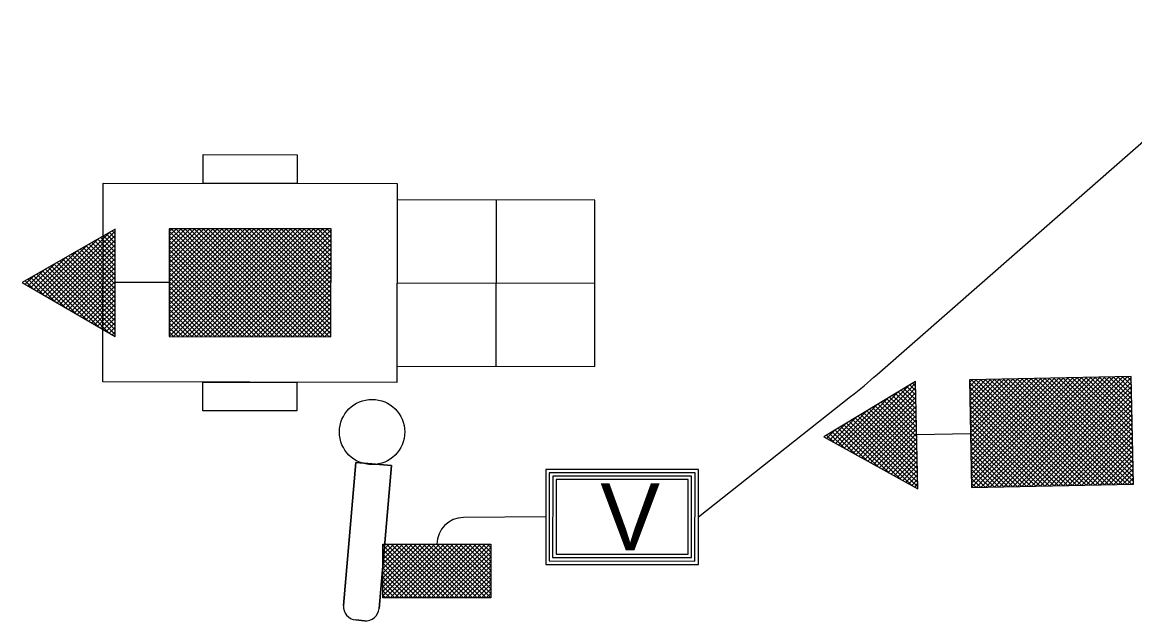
# Model space of a CAD drawing. Extents: x 584850 to 602551, y 145475 to 158627.
# Drawn here: x 585770 to 585852.5, y 152623.4 to 152667.8 of the extents above; entities that cross this region are included whole.
import ezdxf

# ---------------------------------------------------------------- set-up
doc = ezdxf.new("R2010")
doc.units = 0
doc.layers.add('Default', color=7, linetype='Continuous')

msp = doc.modelspace()

# ---------------------------------------------------------------- linework, layer by layer
at = {"layer": 'Default'}
for p, q in [((585833.355, 152641.699), (585863.133, 152667.828)), ((585805.092, 152654.647), (585805.071, 152642.296)), ((585771.677, 152647.517), (585776.391, 152652.214)), ((585771.892, 152647.392), (585776.857, 152652.341)), ((585772.107, 152647.267), (585776.857, 152652.001)), ((585776.855, 152650.773), (585775.773, 152651.858)), ((585776.855, 152651.113), (585775.988, 152651.983)), ((585776.856, 152651.452), (585776.203, 152652.106)), ((585776.856, 152651.792), (585776.419, 152652.23)), ((585776.857, 152652.131), (585776.634, 152652.354)), ((585776.857, 152652.47), (585776.849, 152652.478)), ((585780.843, 152644.513), (585788.857, 152652.499)), ((585780.844, 152645.192), (585788.178, 152652.501)), ((585780.844, 152644.853), (585788.518, 152652.5)), ((585780.845, 152645.531), (585787.839, 152652.501)), ((585780.846, 152646.21), (585787.16, 152652.502)), ((585780.846, 152645.871), (585787.5, 152652.502)), ((585780.847, 152646.889), (585786.481, 152652.504)), ((585780.847, 152646.55), (585786.821, 152652.503)), ((585780.848, 152647.229), (585786.142, 152652.504)), ((585780.849, 152647.907), (585785.463, 152652.505)), ((585780.849, 152647.568), (585785.803, 152652.505)), ((585780.85, 152648.247), (585785.124, 152652.506)), ((585780.85, 152648.586), (585784.784, 152652.506)), ((585780.851, 152649.265), (585784.105, 152652.508)), ((585780.851, 152648.926), (585784.445, 152652.507)), ((585780.852, 152649.604), (585783.766, 152652.508)), ((585780.853, 152649.944), (585783.427, 152652.509)), ((585780.853, 152650.283), (585783.087, 152652.509)), ((585780.854, 152650.962), (585782.408, 152652.511)), ((585780.854, 152650.623), (585782.748, 152652.51)), ((585780.855, 152651.301), (585782.069, 152652.511)), ((585780.856, 152651.641), (585781.73, 152652.512)), ((585780.856, 152651.98), (585781.39, 152652.512)), ((585788.31, 152644.5), (585780.856, 152651.98)), ((585780.857, 152652.32), (585781.051, 152652.513)), ((585788.65, 152644.5), (585780.857, 152652.32)), ((585788.989, 152644.499), (585781.003, 152652.513)), ((585781.183, 152644.513), (585789.197, 152652.499)), ((585789.329, 152644.499), (585781.343, 152652.512)), ((585781.522, 152644.512), (585789.536, 152652.498)), ((585789.668, 152644.498), (585781.682, 152652.512)), ((585781.861, 152644.511), (585789.875, 152652.498)), ((585790.007, 152644.497), (585782.021, 152652.511)), ((585782.201, 152644.511), (585790.215, 152652.497)), ((585790.347, 152644.497), (585782.361, 152652.511)), ((585782.54, 152644.51), (585790.554, 152652.497)), ((585790.686, 152644.496), (585782.7, 152652.51)), ((585782.88, 152644.51), (585790.894, 152652.496)), ((585791.026, 152644.496), (585783.04, 152652.509)), ((585783.219, 152644.509), (585791.233, 152652.495)), ((585791.365, 152644.495), (585783.379, 152652.509)), ((585783.559, 152644.509), (585791.573, 152652.495)), ((585791.704, 152644.495), (585783.718, 152652.508)), ((585783.898, 152644.508), (585791.912, 152652.494)), ((585792.044, 152644.494), (585784.058, 152652.508)), ((585784.237, 152644.507), (585792.251, 152652.494)), ((585792.383, 152644.493), (585784.397, 152652.507)), ((585784.577, 152644.507), (585792.591, 152652.493)), ((585792.723, 152644.493), (585784.737, 152652.507)), ((585784.916, 152644.506), (585792.857, 152652.42)), ((585792.844, 152644.711), (585785.076, 152652.506)), ((585785.256, 152644.506), (585792.857, 152652.081)), ((585792.845, 152645.05), (585785.415, 152652.505)), ((585792.845, 152645.39), (585785.755, 152652.505)), ((585792.846, 152645.729), (585786.094, 152652.504)), ((585792.847, 152646.069), (585786.434, 152652.504)), ((585792.847, 152646.408), (585786.773, 152652.503)), ((585792.848, 152646.748), (585787.113, 152652.502)), ((585792.848, 152647.087), (585787.452, 152652.502)), ((585792.849, 152647.426), (585787.791, 152652.501)), ((585792.849, 152647.766), (585788.131, 152652.501)), ((585792.85, 152648.105), (585788.47, 152652.5)), ((585792.851, 152648.445), (585788.81, 152652.5)), ((585792.851, 152648.784), (585789.149, 152652.499)), ((585792.852, 152649.123), (585789.488, 152652.498)), ((585792.852, 152649.463), (585789.828, 152652.498)), ((585792.853, 152649.802), (585790.167, 152652.497)), ((585792.853, 152650.142), (585790.507, 152652.497)), ((585792.854, 152650.481), (585790.846, 152652.496)), ((585792.855, 152650.82), (585791.185, 152652.495)), ((585792.855, 152651.16), (585791.525, 152652.495)), ((585792.856, 152651.499), (585791.864, 152652.494)), ((585792.856, 152651.839), (585792.204, 152652.494)), ((585792.857, 152652.178), (585792.543, 152652.493)), ((585771.247, 152647.766), (585774.782, 152651.289)), ((585771.462, 152647.641), (585775.586, 152651.751)), ((585772.322, 152647.143), (585776.856, 152651.662)), ((585772.537, 152647.018), (585776.855, 152651.322)), ((585776.851, 152648.737), (585774.481, 152651.115)), ((585776.852, 152649.076), (585774.696, 152651.239)), ((585776.852, 152649.416), (585774.911, 152651.363)), ((585776.853, 152649.755), (585775.127, 152651.487)), ((585776.853, 152650.095), (585775.342, 152651.611)), ((585776.854, 152650.434), (585775.557, 152651.735)), ((585787.631, 152644.502), (585780.855, 152651.301)), ((585787.971, 152644.501), (585780.856, 152651.641)), ((585785.595, 152644.505), (585792.856, 152651.741)), ((585785.934, 152644.504), (585792.856, 152651.402)), ((585786.274, 152644.504), (585792.855, 152651.063)), ((585770.817, 152648.015), (585773.174, 152650.364)), ((585771.032, 152647.891), (585773.978, 152650.826)), ((585772.751, 152646.894), (585776.855, 152650.983)), ((585772.967, 152646.769), (585776.854, 152650.643)), ((585776.847, 152646.361), (585772.973, 152650.248)), ((585773.181, 152646.644), (585776.854, 152650.304)), ((585776.848, 152646.7), (585773.188, 152650.372)), ((585776.848, 152647.04), (585773.404, 152650.496)), ((585776.849, 152647.379), (585773.619, 152650.62)), ((585776.849, 152647.719), (585773.834, 152650.744)), ((585776.85, 152648.058), (585774.05, 152650.867)), ((585776.85, 152648.397), (585774.265, 152650.991)), ((585786.613, 152644.503), (585780.853, 152650.283)), ((585787.292, 152644.502), (585780.854, 152650.962)), ((585786.953, 152644.503), (585780.854, 152650.623)), ((585786.613, 152644.503), (585792.854, 152650.723)), ((585786.953, 152644.503), (585792.854, 152650.384)), ((585770.388, 152648.265), (585771.566, 152649.439)), ((585770.603, 152648.14), (585772.37, 152649.901)), ((585775.578, 152645.254), (585771.465, 152649.381)), ((585776.381, 152644.788), (585771.681, 152649.505)), ((585776.844, 152644.664), (585771.896, 152649.629)), ((585776.845, 152645.003), (585772.111, 152649.753)), ((585776.845, 152645.343), (585772.327, 152649.876)), ((585776.846, 152645.682), (585772.542, 152650)), ((585776.846, 152646.022), (585772.757, 152650.124)), ((585773.396, 152646.519), (585776.853, 152649.965)), ((585773.611, 152646.395), (585776.853, 152649.625)), ((585785.934, 152644.504), (585780.852, 152649.604)), ((585786.274, 152644.504), (585780.853, 152649.944)), ((585787.292, 152644.502), (585792.853, 152650.044)), ((585787.631, 152644.502), (585792.853, 152649.705)), ((585787.971, 152644.501), (585792.852, 152649.366)), ((585770.172, 152648.389), (585770.762, 152648.976)), ((585770.76, 152648.048), (585770.173, 152648.637)), ((585771.564, 152647.583), (585770.389, 152648.762)), ((585772.366, 152647.117), (585770.604, 152648.885)), ((585773.169, 152646.651), (585770.819, 152649.009)), ((585773.972, 152646.185), (585771.035, 152649.133)), ((585774.775, 152645.72), (585771.25, 152649.257)), ((585773.826, 152646.27), (585776.852, 152649.286)), ((585774.041, 152646.145), (585776.851, 152648.946)), ((585774.256, 152646.021), (585776.851, 152648.607)), ((585784.916, 152644.506), (585780.85, 152648.586)), ((585785.595, 152644.505), (585780.851, 152649.265)), ((585785.256, 152644.506), (585780.851, 152648.926)), ((585788.31, 152644.5), (585792.852, 152649.026)), ((585788.65, 152644.5), (585792.851, 152648.687)), ((585769.958, 152648.514), (585769.958, 152648.514)), ((585774.471, 152645.896), (585776.85, 152648.268)), ((585774.686, 152645.772), (585776.85, 152647.928)), ((585780.85, 152648.513), (585776.851, 152648.52)), ((585784.237, 152644.507), (585780.849, 152647.907)), ((585784.577, 152644.507), (585780.85, 152648.247)), ((585788.989, 152644.499), (585792.85, 152648.347)), ((585789.329, 152644.499), (585792.85, 152648.008)), ((585812.418, 152648.459), (585797.744, 152648.484)), ((585774.901, 152645.647), (585776.849, 152647.589)), ((585775.116, 152645.523), (585776.849, 152647.249)), ((585775.331, 152645.398), (585776.848, 152646.91)), ((585783.219, 152644.509), (585780.847, 152646.889)), ((585783.559, 152644.509), (585780.848, 152647.229)), ((585783.898, 152644.508), (585780.849, 152647.568)), ((585789.668, 152644.498), (585792.849, 152647.669)), ((585790.007, 152644.497), (585792.849, 152647.329)), ((585790.347, 152644.497), (585792.848, 152646.99)), ((585775.546, 152645.273), (585776.847, 152646.571)), ((585775.76, 152645.148), (585776.847, 152646.231)), ((585782.54, 152644.51), (585780.846, 152646.21)), ((585782.88, 152644.51), (585780.847, 152646.55)), ((585790.686, 152644.496), (585792.848, 152646.65)), ((585791.026, 152644.496), (585792.847, 152646.311)), ((585775.975, 152645.024), (585776.846, 152645.892)), ((585776.19, 152644.899), (585776.846, 152645.552)), ((585781.861, 152644.511), (585780.845, 152645.531)), ((585782.201, 152644.511), (585780.846, 152645.871)), ((585791.365, 152644.495), (585792.846, 152645.972)), ((585791.704, 152644.495), (585792.846, 152645.632)), ((585792.044, 152644.494), (585792.845, 152645.293)), ((585776.405, 152644.774), (585776.845, 152645.213)), ((585776.62, 152644.65), (585776.844, 152644.874)), ((585776.835, 152644.525), (585776.844, 152644.534)), ((585781.522, 152644.512), (585780.844, 152645.192)), ((585781.183, 152644.513), (585780.844, 152644.853)), ((585792.383, 152644.493), (585792.845, 152644.953)), ((585792.723, 152644.493), (585792.844, 152644.614)), ((585836.198, 152641.173), (585836.19, 152641.181)), ((585840.2, 152641.111), (585840.389, 152641.308)), ((585848.164, 152633.465), (585840.2, 152641.111)), ((585840.207, 152640.771), (585840.729, 152641.315)), ((585840.214, 152640.432), (585841.068, 152641.322)), ((585840.221, 152640.093), (585841.408, 152641.329)), ((585840.228, 152639.754), (585841.747, 152641.336)), ((585840.235, 152639.414), (585842.086, 152641.343)), ((585840.241, 152639.075), (585842.426, 152641.35)), ((585840.248, 152638.735), (585842.765, 152641.357)), ((585840.255, 152638.396), (585843.104, 152641.364)), ((585840.262, 152638.057), (585843.443, 152641.371)), ((585840.269, 152637.718), (585843.783, 152641.377)), ((585840.276, 152637.378), (585844.122, 152641.384)), ((585840.283, 152637.039), (585844.462, 152641.391)), ((585840.29, 152636.699), (585844.801, 152641.398)), ((585840.297, 152636.36), (585845.14, 152641.405)), ((585840.304, 152636.021), (585845.479, 152641.412)), ((585840.311, 152635.682), (585845.819, 152641.419)), ((585840.318, 152635.342), (585846.158, 152641.426)), ((585840.324, 152635.003), (585846.498, 152641.433)), ((585840.331, 152634.663), (585846.837, 152641.44)), ((585840.338, 152634.324), (585847.177, 152641.447)), ((585848.503, 152633.472), (585840.342, 152641.307)), ((585840.345, 152633.985), (585847.515, 152641.454)), ((585840.352, 152633.645), (585847.855, 152641.46)), ((585840.359, 152633.306), (585848.194, 152641.467)), ((585848.843, 152633.479), (585840.681, 152641.314)), ((585840.698, 152633.313), (585848.534, 152641.474)), ((585849.182, 152633.486), (585841.02, 152641.321)), ((585841.038, 152633.32), (585848.873, 152641.481)), ((585849.521, 152633.493), (585841.36, 152641.328)), ((585841.377, 152633.327), (585849.212, 152641.488)), ((585849.861, 152633.5), (585841.699, 152641.335)), ((585841.716, 152633.334), (585849.552, 152641.495)), ((585850.2, 152633.507), (585842.039, 152641.342)), ((585842.056, 152633.341), (585849.891, 152641.502)), ((585850.539, 152633.514), (585842.378, 152641.349)), ((585842.395, 152633.348), (585850.23, 152641.509)), ((585850.878, 152633.52), (585842.717, 152641.356)), ((585842.735, 152633.354), (585850.57, 152641.516)), ((585851.218, 152633.527), (585843.056, 152641.363)), ((585843.074, 152633.361), (585850.909, 152641.523)), ((585851.557, 152633.534), (585843.396, 152641.37)), ((585843.413, 152633.368), (585851.248, 152641.53)), ((585851.897, 152633.541), (585843.735, 152641.376)), ((585843.752, 152633.375), (585851.588, 152641.537)), ((585852.236, 152633.548), (585844.075, 152641.383)), ((585844.092, 152633.382), (585851.927, 152641.543)), ((585852.353, 152633.769), (585844.414, 152641.39)), ((585844.431, 152633.389), (585852.195, 152641.476)), ((585852.346, 152634.108), (585844.753, 152641.397)), ((585844.771, 152633.396), (585852.202, 152641.137)), ((585852.339, 152634.447), (585845.092, 152641.404)), ((585852.332, 152634.787), (585845.432, 152641.411)), ((585852.325, 152635.126), (585845.771, 152641.418)), ((585852.318, 152635.466), (585846.111, 152641.425)), ((585852.311, 152635.805), (585846.45, 152641.432)), ((585852.304, 152636.144), (585846.789, 152641.439)), ((585852.297, 152636.483), (585847.129, 152641.446)), ((585852.29, 152636.823), (585847.468, 152641.453)), ((585852.283, 152637.162), (585847.807, 152641.459)), ((585852.276, 152637.502), (585848.147, 152641.466)), ((585852.27, 152637.841), (585848.486, 152641.473)), ((585852.263, 152638.18), (585848.825, 152641.48)), ((585852.256, 152638.52), (585849.165, 152641.487)), ((585852.249, 152638.859), (585849.504, 152641.494)), ((585852.242, 152639.198), (585849.843, 152641.501)), ((585852.235, 152639.538), (585850.183, 152641.508)), ((585852.228, 152639.877), (585850.522, 152641.515)), ((585852.221, 152640.216), (585850.861, 152641.522)), ((585852.214, 152640.556), (585851.201, 152641.529)), ((585852.207, 152640.895), (585851.54, 152641.536)), ((585852.2, 152641.234), (585851.88, 152641.543)), ((585830.911, 152636.226), (585834.943, 152640.426)), ((585831.129, 152636.106), (585835.737, 152640.906)), ((585831.346, 152635.986), (585836.201, 152641.043)), ((585831.564, 152635.866), (585836.208, 152640.704)), ((585831.781, 152635.747), (585836.215, 152640.364)), ((585836.24, 152639.137), (585834.915, 152640.409)), ((585836.233, 152639.476), (585835.128, 152640.537)), ((585836.226, 152639.816), (585835.34, 152640.666)), ((585836.219, 152640.155), (585835.552, 152640.795)), ((585836.212, 152640.494), (585835.765, 152640.923)), ((585836.205, 152640.833), (585835.978, 152641.052)), ((585847.824, 152633.458), (585840.207, 152640.771)), ((585847.485, 152633.451), (585840.214, 152640.432)), ((585845.11, 152633.403), (585852.209, 152640.798)), ((585845.449, 152633.41), (585852.216, 152640.459)), ((585820.095, 152631.133), (585831.385, 152640.059)), ((585830.476, 152636.466), (585833.356, 152639.466)), ((585830.694, 152636.346), (585834.149, 152639.946)), ((585831.999, 152635.627), (585836.222, 152640.025)), ((585832.216, 152635.507), (585836.229, 152639.686)), ((585836.288, 152636.762), (585833.427, 152639.508)), ((585836.281, 152637.101), (585833.639, 152639.637)), ((585836.274, 152637.44), (585833.852, 152639.766)), ((585836.267, 152637.78), (585834.064, 152639.895)), ((585836.261, 152638.119), (585834.277, 152640.023)), ((585836.254, 152638.458), (585834.49, 152640.152)), ((585836.247, 152638.798), (585834.702, 152640.28)), ((585847.146, 152633.444), (585840.221, 152640.093)), ((585846.807, 152633.437), (585840.228, 152639.754)), ((585845.788, 152633.417), (585852.223, 152640.119)), ((585846.128, 152633.424), (585852.23, 152639.78)), ((585830.258, 152636.586), (585832.562, 152638.986)), ((585836.33, 152634.726), (585832.151, 152638.737)), ((585836.323, 152635.065), (585832.364, 152638.866)), ((585832.434, 152635.387), (585836.236, 152639.346)), ((585836.316, 152635.404), (585832.576, 152638.994)), ((585832.652, 152635.267), (585836.242, 152639.007)), ((585836.309, 152635.743), (585832.789, 152639.123)), ((585832.869, 152635.147), (585836.249, 152638.668)), ((585836.302, 152636.083), (585833.002, 152639.251)), ((585836.295, 152636.422), (585833.214, 152639.38)), ((585846.467, 152633.431), (585840.235, 152639.414)), ((585846.128, 152633.424), (585840.241, 152639.075)), ((585845.788, 152633.417), (585840.248, 152638.735)), ((585846.467, 152633.431), (585852.237, 152639.44)), ((585846.807, 152633.437), (585852.244, 152639.101)), ((585847.146, 152633.444), (585852.251, 152638.762)), ((585829.823, 152636.825), (585830.975, 152638.025)), ((585830.041, 152636.705), (585831.769, 152638.505)), ((585834.265, 152634.379), (585830.663, 152637.837)), ((585835.079, 152633.931), (585830.876, 152637.965)), ((585835.891, 152633.482), (585831.089, 152638.094)), ((585836.357, 152633.368), (585831.301, 152638.222)), ((585836.351, 152633.707), (585831.513, 152638.351)), ((585836.344, 152634.047), (585831.726, 152638.48)), ((585836.337, 152634.386), (585831.939, 152638.608)), ((585833.087, 152635.028), (585836.256, 152638.328)), ((585833.305, 152634.908), (585836.263, 152637.989)), ((585845.449, 152633.41), (585840.255, 152638.396)), ((585845.11, 152633.403), (585840.262, 152638.057)), ((585847.485, 152633.451), (585852.258, 152638.423)), ((585847.824, 152633.458), (585852.265, 152638.083)), ((585829.388, 152637.065), (585829.388, 152637.065)), ((585830.2, 152636.617), (585829.6, 152637.194)), ((585829.605, 152636.945), (585830.182, 152637.545)), ((585831.014, 152636.17), (585829.813, 152637.322)), ((585831.827, 152635.722), (585830.025, 152637.451)), ((585832.64, 152635.274), (585830.238, 152637.58)), ((585833.453, 152634.826), (585830.451, 152637.708)), ((585833.522, 152634.787), (585836.27, 152637.65)), ((585833.74, 152634.668), (585836.277, 152637.311)), ((585840.277, 152637.305), (585836.279, 152637.224)), ((585844.771, 152633.396), (585840.269, 152637.718)), ((585844.431, 152633.389), (585840.276, 152637.378)), ((585844.092, 152633.382), (585840.283, 152637.039)), ((585848.164, 152633.465), (585852.272, 152637.744)), ((585848.503, 152633.472), (585852.278, 152637.404)), ((585848.843, 152633.479), (585852.285, 152637.065)), ((585833.958, 152634.548), (585836.284, 152636.971)), ((585834.175, 152634.428), (585836.291, 152636.632)), ((585834.393, 152634.308), (585836.298, 152636.292)), ((585843.752, 152633.375), (585840.29, 152636.699)), ((585843.413, 152633.368), (585840.297, 152636.36)), ((585849.182, 152633.486), (585852.292, 152636.726)), ((585849.521, 152633.493), (585852.299, 152636.386)), ((585834.61, 152634.189), (585836.305, 152635.953)), ((585834.828, 152634.068), (585836.312, 152635.613)), ((585843.074, 152633.361), (585840.304, 152636.021)), ((585842.735, 152633.354), (585840.311, 152635.682)), ((585842.395, 152633.348), (585840.318, 152635.342)), ((585849.861, 152633.5), (585852.306, 152636.047)), ((585850.2, 152633.507), (585852.313, 152635.708)), ((585850.539, 152633.514), (585852.32, 152635.368)), ((585835.046, 152633.948), (585836.319, 152635.275)), ((585835.263, 152633.829), (585836.325, 152634.935)), ((585835.481, 152633.709), (585836.332, 152634.596)), ((585842.056, 152633.341), (585840.324, 152635.003)), ((585841.716, 152633.334), (585840.331, 152634.663)), ((585850.878, 152633.52), (585852.327, 152635.029)), ((585851.218, 152633.527), (585852.334, 152634.69)), ((585835.699, 152633.589), (585836.339, 152634.256)), ((585835.916, 152633.469), (585836.346, 152633.917)), ((585841.377, 152633.327), (585840.338, 152634.324)), ((585841.038, 152633.32), (585840.345, 152633.985)), ((585851.557, 152633.534), (585852.341, 152634.35)), ((585851.897, 152633.541), (585852.348, 152634.011)), ((585836.134, 152633.349), (585836.353, 152633.578)), ((585836.351, 152633.229), (585836.36, 152633.238)), ((585840.698, 152633.313), (585840.352, 152633.645)), ((585852.236, 152633.548), (585852.355, 152633.672)), ((585808.791, 152631.136), (585802.689, 152631.092)), ((585796.703, 152625.267), (585800.557, 152629.121)), ((585796.703, 152627.303), (585798.521, 152629.121)), ((585796.703, 152625.606), (585800.218, 152629.121)), ((585796.703, 152627.642), (585798.182, 152629.121)), ((585796.703, 152625.945), (585799.879, 152629.121)), ((585796.703, 152627.982), (585797.842, 152629.121)), ((585796.703, 152626.285), (585799.539, 152629.121)), ((585796.703, 152628.321), (585797.503, 152629.121)), ((585796.703, 152626.624), (585799.2, 152629.121)), ((585796.703, 152628.661), (585797.163, 152629.121)), ((585796.703, 152626.964), (585798.86, 152629.121)), ((585796.703, 152629), (585796.824, 152629.121)), ((585800.63, 152625.121), (585796.703, 152629.048)), ((585796.897, 152625.121), (585800.897, 152629.121)), ((585800.97, 152625.121), (585796.97, 152629.121)), ((585797.236, 152625.121), (585801.236, 152629.121)), ((585801.309, 152625.121), (585797.309, 152629.121)), ((585797.576, 152625.121), (585801.576, 152629.121)), ((585801.649, 152625.121), (585797.649, 152629.121)), ((585797.915, 152625.121), (585801.915, 152629.121)), ((585801.988, 152625.121), (585797.988, 152629.121)), ((585798.254, 152625.121), (585802.254, 152629.121)), ((585802.327, 152625.121), (585798.327, 152629.121)), ((585798.594, 152625.121), (585802.594, 152629.121)), ((585802.667, 152625.121), (585798.667, 152629.121)), ((585798.933, 152625.121), (585802.933, 152629.121)), ((585803.006, 152625.121), (585799.006, 152629.121)), ((585799.273, 152625.121), (585803.273, 152629.121)), ((585803.346, 152625.121), (585799.346, 152629.121)), ((585799.612, 152625.121), (585803.612, 152629.121)), ((585803.685, 152625.121), (585799.685, 152629.121)), ((585799.951, 152625.121), (585803.951, 152629.121)), ((585804.024, 152625.121), (585800.024, 152629.121)), ((585800.291, 152625.121), (585804.291, 152629.121)), ((585804.364, 152625.121), (585800.364, 152629.121)), ((585800.63, 152625.121), (585804.63, 152629.121)), ((585804.703, 152625.121), (585800.703, 152629.121)), ((585800.97, 152625.121), (585804.703, 152628.854)), ((585804.703, 152625.46), (585801.043, 152629.121)), ((585804.703, 152625.8), (585801.382, 152629.121)), ((585804.703, 152626.139), (585801.721, 152629.121)), ((585804.703, 152626.478), (585802.061, 152629.121)), ((585804.703, 152626.818), (585802.4, 152629.121)), ((585804.703, 152627.157), (585802.74, 152629.121)), ((585804.703, 152627.497), (585803.079, 152629.121)), ((585804.703, 152627.836), (585803.419, 152629.121)), ((585804.703, 152628.175), (585803.758, 152629.121)), ((585804.703, 152628.515), (585804.097, 152629.121)), ((585804.703, 152628.854), (585804.437, 152629.121)), ((585800.291, 152625.121), (585796.703, 152628.708)), ((585799.951, 152625.121), (585796.703, 152628.369)), ((585799.612, 152625.121), (585796.703, 152628.03)), ((585801.309, 152625.121), (585804.703, 152628.515)), ((585801.649, 152625.121), (585804.703, 152628.175)), ((585799.273, 152625.121), (585796.703, 152627.69)), ((585798.933, 152625.121), (585796.703, 152627.351)), ((585801.988, 152625.121), (585804.703, 152627.836)), ((585802.327, 152625.121), (585804.703, 152627.497)), ((585802.667, 152625.121), (585804.703, 152627.157)), ((585798.594, 152625.121), (585796.703, 152627.011)), ((585798.254, 152625.121), (585796.703, 152626.672)), ((585797.915, 152625.121), (585796.703, 152626.333)), ((585803.006, 152625.121), (585804.703, 152626.818)), ((585803.346, 152625.121), (585804.703, 152626.478)), ((585797.576, 152625.121), (585796.703, 152625.993)), ((585797.236, 152625.121), (585796.703, 152625.654)), ((585803.685, 152625.121), (585804.703, 152626.139)), ((585804.024, 152625.121), (585804.703, 152625.8)), ((585804.364, 152625.121), (585804.703, 152625.46)), ((585796.897, 152625.121), (585796.703, 152625.314))]:
    msp.add_line(p, q, dxfattribs=at)
for points in [[(585790.356, 152658.002), (585790.352, 152655.866), (585783.374, 152655.878), (585783.378, 152658.014)], [(585797.757, 152655.854), (585797.732, 152641.115), (585775.944, 152641.152), (585775.969, 152655.891)], [(585812.429, 152654.635), (585797.755, 152654.66), (585797.734, 152642.309), (585812.408, 152642.283)], [(585776.844, 152644.52), (585776.857, 152652.483), (585769.958, 152648.514)], [(585792.858, 152652.493), (585780.857, 152652.513), (585780.843, 152644.513), (585792.844, 152644.493)], [(585790.327, 152641.127), (585790.323, 152638.991), (585783.345, 152639.003), (585783.349, 152641.139)], [(585836.36, 152633.224), (585836.198, 152641.185), (585829.388, 152637.065)], [(585852.194, 152641.549), (585840.196, 152641.304), (585840.359, 152633.306), (585852.357, 152633.551)], [(585820.096, 152634.655), (585808.792, 152634.658), (585808.79, 152627.614), (585820.094, 152627.611)], [(585819.846, 152634.405), (585809.042, 152634.408), (585809.04, 152627.864), (585819.844, 152627.861)], [(585819.596, 152634.155), (585809.292, 152634.158), (585809.29, 152628.113), (585819.594, 152628.111)], [(585819.346, 152633.906), (585809.542, 152633.908), (585809.54, 152628.363), (585819.344, 152628.361)], [(585796.703, 152629.121), (585804.703, 152629.121), (585804.703, 152625.121), (585796.703, 152625.121)]]:
    msp.add_lwpolyline(points, close=True, dxfattribs=at)
for points in [[(585793.773, 152624.574), (585794.694, 152635.176), (585797.345, 152634.946), (585796.424, 152624.344)], [(585796.424, 152624.344), (585797.345, 152634.946), (585794.694, 152635.176), (585793.773, 152624.574)], [(585795.342, 152623.434), (585794.683, 152623.491)], [(585794.683, 152623.491), (585795.342, 152623.434)]]:
    msp.add_lwpolyline(points, dxfattribs=at)
msp.add_circle((585795.897, 152637.433), 2.42, dxfattribs=at)
for centre, radius, start, end in [((585800.377, 152679.282), 50, 308.32811, 311.26536), ((585802.703, 152629.092), 2, 90.41315, 179.18135), ((585794.77, 152624.487), 1, 175.03749, 265.03749), ((585794.77, 152624.487), 1, 175.03749, 265.03749), ((585795.428, 152624.43), 1, 265.03749, 355.03749), ((585795.428, 152624.43), 1, 265.03749, 355.03749)]:
    msp.add_arc(centre, radius, start, end, dxfattribs=at)

# ---------------------------------------------------------------- texts
msp.add_text('V', height=4.958, rotation=359.98539, dxfattribs=at).set_placement((585812.822, 152628.656))

doc.saveas('drawing.dxf')
